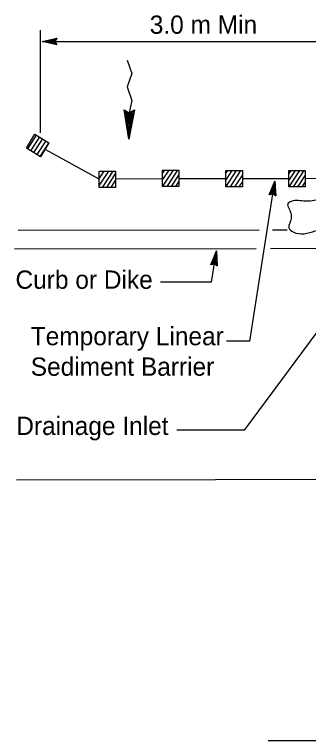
# Model space of a CAD drawing. Extents: x 6707406 to 6714471, y 1868570 to 1872341.
# Drawn here: x 6709577.4 to 6709693.1, y 1871429.7 to 1871715.5 of the extents above; entities that cross this region are included whole.
import ezdxf

# ---------------------------------------------------------------- set-up
doc = ezdxf.new("R2010")
doc.units = 0
for name, color, linetype in [('1 Control', 7, 'Continuous'), ('57 Undefined', 7, 'Continuous'), ('60 Nongeo Data', 7, 'Continuous'), ('63 Undefined', 7, 'Continuous')]:
    doc.layers.add(name, color=color, linetype=linetype)

msp = doc.modelspace()

# ---------------------------------------------------------------- linework, layer by layer
at = {"layer": '1 Control'}
for p, q in [((6709586, 1871668.01), (6709582.49, 1871662.61)), ((6709587.23, 1871667.27), (6709583.72, 1871661.86)), ((6709588.46, 1871666.52), (6709584.95, 1871661.12)), ((6709589.69, 1871665.77), (6709586.18, 1871660.37)), ((6709590.92, 1871665.03), (6709587.42, 1871659.62)), ((6709614.35, 1871653.84), (6709610.79, 1871648.35)), ((6709612.63, 1871653.84), (6709610.79, 1871650.99)), ((6709610.92, 1871653.84), (6709610.79, 1871653.64)), ((6709616.07, 1871653.84), (6709611.89, 1871647.4)), ((6709617.22, 1871652.97), (6709613.6, 1871647.4)), ((6709639.86, 1871654.22), (6709635.72, 1871647.85)), ((6709638.14, 1871654.22), (6709635.72, 1871650.5)), ((6709636.43, 1871654.22), (6709635.72, 1871653.14)), ((6709641.58, 1871654.22), (6709637.4, 1871647.78)), ((6709642.16, 1871652.47), (6709639.11, 1871647.78)), ((6709664.71, 1871654.03), (6709660.66, 1871647.8)), ((6709662.99, 1871654.03), (6709660.66, 1871650.44)), ((6709661.28, 1871654.03), (6709660.66, 1871653.09)), ((6709666.43, 1871654.03), (6709662.25, 1871647.59)), ((6709689.59, 1871654.03), (6709685.41, 1871647.6)), ((6709687.87, 1871654.03), (6709685.41, 1871650.24)), ((6709686.16, 1871654.03), (6709685.41, 1871652.89)), ((6709691.31, 1871654.03), (6709687.12, 1871647.59)), ((6709617.22, 1871650.33), (6709615.32, 1871647.4)), ((6709642.16, 1871649.83), (6709640.83, 1871647.78)), ((6709667.1, 1871652.42), (6709663.96, 1871647.59)), ((6709667.1, 1871649.78), (6709665.68, 1871647.59)), ((6709691.85, 1871652.22), (6709688.84, 1871647.59)), ((6709617.22, 1871647.69), (6709617.04, 1871647.4)), ((6709691.85, 1871649.58), (6709690.56, 1871647.59))]:
    msp.add_line(p, q, dxfattribs=at)
for points in [[(6709585.47, 1871668.33), (6709590.98, 1871664.99), (6709587.64, 1871659.49), (6709582.14, 1871662.83)], [(6709610.79, 1871653.84), (6709617.22, 1871653.84), (6709617.22, 1871647.4), (6709610.79, 1871647.4)], [(6709635.72, 1871654.22), (6709642.16, 1871654.22), (6709642.16, 1871647.78), (6709635.72, 1871647.78)], [(6709660.66, 1871654.03), (6709667.1, 1871654.03), (6709667.1, 1871647.59), (6709660.66, 1871647.59)], [(6709685.41, 1871654.03), (6709691.85, 1871654.03), (6709691.85, 1871647.59), (6709685.41, 1871647.59)]]:
    msp.add_lwpolyline(points, close=True, dxfattribs=at)
at = {"layer": '57 Undefined'}
for p, q in [((6709587.7, 1871668.85), (6709587.7, 1871709.29)), ((6709588.34, 1871704.86), (6709715.63, 1871704.86)), ((6709670.02, 1871586.95), (6709679.85, 1871649.92)), ((6709654.95, 1871610.12), (6709656.87, 1871622.41)), ((6709654.95, 1871610.12), (6709634.94, 1871610.12)), ((6709668.01, 1871551.82), (6709699.53, 1871594.51)), ((6709670.02, 1871586.95), (6709660.85, 1871586.95)), ((6709668.01, 1871551.82), (6709641.29, 1871551.82)), ((6709677.29, 1871429.73), (6709944.39, 1871429.73))]:
    msp.add_line(p, q, dxfattribs=at)
at = {"layer": '60 Nongeo Data'}
for p, q in [((6709588.34, 1871704.86), (6709588.34, 1871704.86)), ((6709594.1, 1871706.14), (6709594.1, 1871706.14)), ((6709594.1, 1871703.58), (6709594.1, 1871703.58)), ((6709679.85, 1871649.92), (6709679.85, 1871649.92)), ((6709677.69, 1871644.43), (6709677.69, 1871644.43)), ((6709680.22, 1871644.03), (6709680.22, 1871644.03)), ((6709656.87, 1871622.41), (6709656.87, 1871622.41)), ((6709654.71, 1871616.91), (6709654.71, 1871616.91)), ((6709657.24, 1871616.52), (6709657.24, 1871616.52))]:
    msp.add_line(p, q, dxfattribs=at)
for points in [[(6709594.1, 1871703.58), (6709588.34, 1871704.86), (6709594.1, 1871706.14), (6709593.9, 1871705.8), (6709589.68, 1871704.87), (6709593.9, 1871703.92), (6709593.7, 1871704.26), (6709591, 1871704.86), (6709593.69, 1871705.46), (6709593.49, 1871705.12), (6709592.32, 1871704.86), (6709593.49, 1871704.6), (6709593.34, 1871704.86), (6709594.1, 1871706.14), (6709593.34, 1871704.86)], [(6709677.69, 1871644.43), (6709679.85, 1871649.92), (6709680.22, 1871644.03), (6709679.92, 1871644.29), (6709679.65, 1871648.6), (6709678.06, 1871644.58), (6709678.43, 1871644.73), (6709679.44, 1871647.3), (6709679.62, 1871644.54), (6709679.31, 1871644.8), (6709679.23, 1871645.99), (6709678.8, 1871644.88), (6709679.08, 1871644.99), (6709680.22, 1871644.03), (6709679.08, 1871644.99)], [(6709654.71, 1871616.91), (6709656.87, 1871622.41), (6709657.24, 1871616.52), (6709656.94, 1871616.77), (6709656.67, 1871621.09), (6709655.08, 1871617.06), (6709655.45, 1871617.21), (6709656.46, 1871619.79), (6709656.63, 1871617.03), (6709656.33, 1871617.28), (6709656.25, 1871618.48), (6709655.82, 1871617.36), (6709656.1, 1871617.47), (6709657.24, 1871616.52), (6709656.1, 1871617.47)]]:
    msp.add_lwpolyline(points, close=True, dxfattribs=at)
for points in [[(6709589.56, 1871662.27), (6709610.62, 1871650.83)], [(6709617.38, 1871650.84), (6709635.47, 1871650.87)], [(6709642.09, 1871650.88), (6709660.59, 1871650.91)], [(6709667.08, 1871650.92), (6709685.38, 1871650.95)], [(6709691.87, 1871650.96), (6709710.37, 1871650.99)], [(6709578.82, 1871630.54), (6709673.67, 1871630.7)], [(6709678.95, 1871630.71), (6709684.77, 1871630.72)], [(6709577.41, 1871623.19), (6709672.55, 1871623.35)], [(6709678.2, 1871623.36), (6709932.4, 1871623.77)], [(6709578.14, 1871532.3), (6710048.25, 1871533.08)]]:
    msp.add_lwpolyline(points, dxfattribs=at)
msp.add_spline([(6709685.81, 1871633.55), (6709685.41, 1871631.49), (6709687.07, 1871629.88), (6709695.81, 1871630.27), (6709699.39, 1871631.08), (6709704.17, 1871630.12), (6709708.12, 1871629.94), (6709708.74, 1871631.23), (6709709.2, 1871640.9), (6709707.25, 1871644.03), (6709703.6, 1871644.06), (6709697.36, 1871642.67), (6709691.88, 1871641.95), (6709686.33, 1871641.92), (6709684.96, 1871640.86), (6709685.47, 1871639.03), (6709686.2, 1871634.53), (6709685.73, 1871633.32)], degree=3, dxfattribs=at)
at = {"layer": '63 Undefined'}
for p, q in [((6709622.46, 1871666.41), (6709620.53, 1871677.97)), ((6709620.53, 1871677.97), (6709622.55, 1871676.77)), ((6709622.48, 1871669.17), (6709621.06, 1871677.64)), ((6709622.51, 1871671.9), (6709621.61, 1871677.32)), ((6709622.54, 1871674.71), (6709622.15, 1871677)), ((6709624.6, 1871677.93), (6709622.46, 1871666.41)), ((6709624.06, 1871677.62), (6709622.48, 1871669.17)), ((6709623.51, 1871677.3), (6709622.51, 1871671.9)), ((6709622.96, 1871676.99), (6709622.54, 1871674.71)), ((6709622.55, 1871676.77), (6709624.6, 1871677.93))]:
    msp.add_line(p, q, dxfattribs=at)
msp.add_lwpolyline([(6709621.79, 1871697.54), (6709623.65, 1871692.24), (6709621.7, 1871686.98), (6709623.55, 1871681.67), (6709622.55, 1871676.77), (6709622.46, 1871666.41)], dxfattribs=at)

# ---------------------------------------------------------------- texts
at = {"layer": '57 Undefined'}
for s, height, p in [('3.0 m Min', 7.2, (6709630.65, 1871707.87)), ('Curb or Dike', 7.1998, (6709577.8, 1871607.51)), ('Temporary Linear', 7.1998, (6709583.81, 1871585.28)), ('Sediment Barrier', 7.1998, (6709583.81, 1871573.28)), ('Drainage Inlet', 7.1998, (6709578.1, 1871549.97))]:
    msp.add_text(s, height=height, dxfattribs=at).set_placement(p)

doc.saveas('drawing.dxf')
